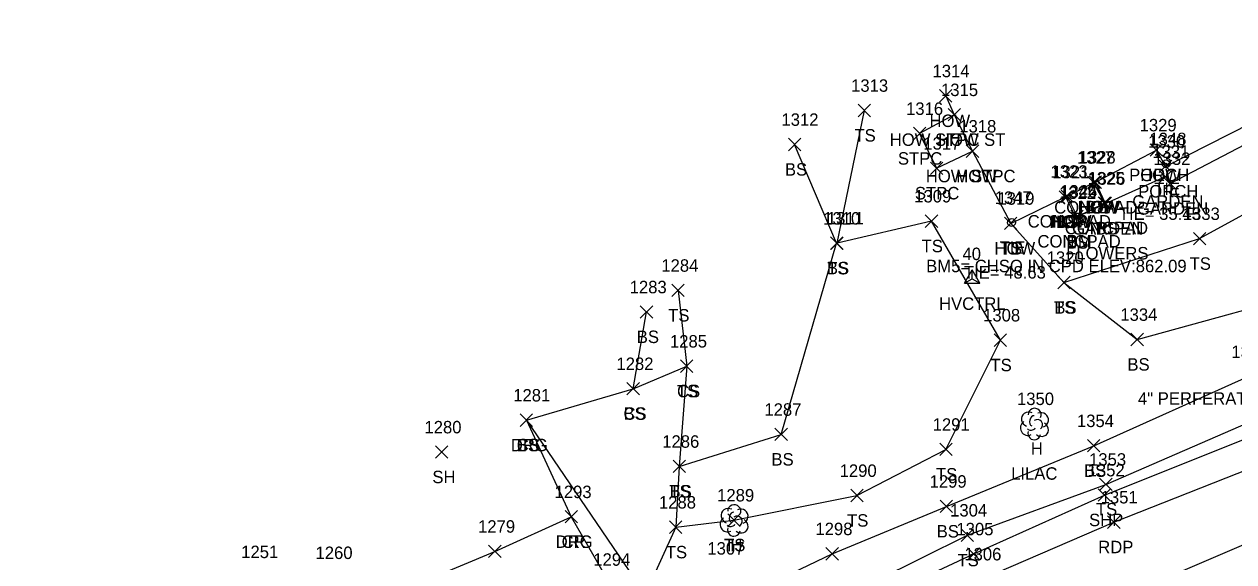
# Model space of a CAD drawing. Extents: x 1606530 to 1613020, y 784959 to 789666.
# Drawn here: x 1608865.5 to 1609059.8, y 788399 to 788485.4 of the extents above; entities that cross this region are included whole.
import ezdxf

# ---------------------------------------------------------------- set-up
doc = ezdxf.new("R2010")
doc.units = 0
for name, color, linetype in [('C_A', 7, 'Continuous'), ('C_C', 7, 'Continuous'), ('C_I', 7, 'Continuous'), ('CBP', 7, 'Continuous'), ('CPBM', 7, 'Continuous'), ('CPSM', 7, 'Continuous'), ('L_A', 7, 'Continuous'), ('L_C', 7, 'Continuous'), ('L_I', 7, 'Continuous'), ('L_TIC', 7, 'Continuous'), ('LAPB', 7, 'Continuous'), ('LBC', 7, 'Continuous'), ('LBF', 7, 'Continuous'), ('LELB', 7, 'Continuous'), ('LS', 7, 'Continuous'), ('LTD', 7, 'Continuous'), ('M_I', 7, 'Continuous'), ('P_A', 7, 'Continuous'), ('P_I', 7, 'Continuous'), ('P_TIC', 7, 'Continuous'), ('PET', 7, 'Continuous'), ('PRC', 7, 'Continuous'), ('PSP', 7, 'Continuous'), ('R_A', 7, 'Continuous'), ('R_I', 7, 'Continuous'), ('R_TIC', 7, 'Continuous'), ('RDG', 7, 'Continuous')]:
    doc.layers.add(name, color=color, linetype=linetype)

msp = doc.modelspace()

# ---------------------------------------------------------------- linework, layer by layer
at = {"layer": 'CBP'}
for centre, radius in [((1609048.95, 788462.92), 0.625), ((1609048.95, 788462.92), 0.0833), ((1609024.11, 788453.49), 0.625), ((1609024.11, 788453.49), 0.0833)]:
    msp.add_circle(centre, radius, dxfattribs=at)
at = {"layer": 'CPBM'}
for p, q in [((1609034.16, 788454.01), (1609034.16, 788455.01)), ((1609034.16, 788455.01), (1609035.16, 788455.01)), ((1609035.16, 788454.01), (1609034.16, 788454.01)), ((1609034.66, 788454.51), (1609034.66, 788454.51)), ((1609034.66, 788454.51), (1609034.66, 788454.51)), ((1609035.16, 788455.01), (1609035.16, 788454.01))]:
    msp.add_line(p, q, dxfattribs=at)
at = {"layer": 'CPSM'}
for p, q in [((1609016.53, 788443.74), (1609017.78, 788445.91)), ((1609016.53, 788443.74), (1609017.78, 788444.46)), ((1609019.03, 788443.74), (1609017.78, 788445.91)), ((1609017.78, 788444.46), (1609017.78, 788445.91)), ((1609017.78, 788444.46), (1609017.78, 788444.46)), ((1609017.78, 788444.46), (1609019.03, 788443.74)), ((1609016.53, 788443.74), (1609019.03, 788443.74))]:
    msp.add_line(p, q, dxfattribs=at)
at = {"layer": 'L_TIC'}
for points in [[(1609012.54, 788472.84), (1609014.54, 788474.84)], [(1609014.54, 788472.84), (1609012.54, 788474.84)], [(1608999.47, 788470.5), (1609001.47, 788472.5)], [(1609001.47, 788470.5), (1608999.47, 788472.5)], [(1609013.92, 788469.81), (1609015.92, 788471.81)], [(1609015.92, 788469.81), (1609013.92, 788471.81)], [(1609013.92, 788469.81), (1609015.92, 788471.81)], [(1609015.92, 788469.81), (1609013.92, 788471.81)], [(1609008.35, 788466.79), (1609010.35, 788468.79)], [(1609010.35, 788466.79), (1609008.35, 788468.79)], [(1608988.27, 788465.03), (1608990.27, 788467.03)], [(1608990.27, 788465.03), (1608988.27, 788467.03)], [(1609016.85, 788463.96), (1609018.85, 788465.96)], [(1609018.85, 788463.96), (1609016.85, 788465.96)], [(1609016.85, 788463.96), (1609018.85, 788465.96)], [(1609018.85, 788463.96), (1609016.85, 788465.96)], [(1609046.39, 788464.14), (1609048.39, 788466.14)], [(1609048.39, 788464.14), (1609046.39, 788466.14)], [(1609046.39, 788464.14), (1609048.39, 788466.14)], [(1609048.39, 788464.14), (1609046.39, 788466.14)], [(1609011.08, 788461.21), (1609013.08, 788463.21)], [(1609013.08, 788461.21), (1609011.08, 788463.21)], [(1609047.84, 788461.52), (1609049.84, 788463.52)], [(1609049.84, 788461.52), (1609047.84, 788463.52)], [(1609047.84, 788459.87), (1609049.84, 788461.87)], [(1609049.84, 788459.87), (1609047.84, 788461.87)], [(1609036.33, 788458.94), (1609038.33, 788460.94)], [(1609038.33, 788458.94), (1609036.33, 788460.94)], [(1609036.33, 788458.94), (1609038.33, 788460.94)], [(1609038.33, 788458.94), (1609036.33, 788460.94)], [(1609036.58, 788458.98), (1609038.58, 788460.98)], [(1609038.58, 788458.98), (1609036.58, 788460.98)], [(1609036.58, 788458.98), (1609038.58, 788460.98)], [(1609038.58, 788458.98), (1609036.58, 788460.98)], [(1609048.6, 788458.75), (1609050.6, 788460.75)], [(1609050.6, 788458.75), (1609048.6, 788460.75)], [(1609031.79, 788456.6), (1609033.79, 788458.6)], [(1609033.79, 788456.6), (1609031.79, 788458.6)], [(1609031.79, 788456.6), (1609033.79, 788458.6)], [(1609033.79, 788456.6), (1609031.79, 788458.6)], [(1609032.07, 788456.69), (1609034.07, 788458.69)], [(1609034.07, 788456.69), (1609032.07, 788458.69)], [(1609032.07, 788456.69), (1609034.07, 788458.69)], [(1609034.07, 788456.69), (1609032.07, 788458.69)], [(1609038.03, 788455.61), (1609040.03, 788457.61)], [(1609040.03, 788455.61), (1609038.03, 788457.61)], [(1609038.19, 788455.56), (1609040.19, 788457.56)], [(1609040.19, 788455.56), (1609038.19, 788457.56)], [(1609038.19, 788455.56), (1609040.19, 788457.56)], [(1609040.19, 788455.56), (1609038.19, 788457.56)], [(1609010.26, 788452.72), (1609012.26, 788454.72)], [(1609012.26, 788452.72), (1609010.26, 788454.72)], [(1609022.98, 788452.35), (1609024.98, 788454.35)], [(1609024.98, 788452.35), (1609022.98, 788454.35)], [(1609022.98, 788452.35), (1609024.98, 788454.35)], [(1609024.98, 788452.35), (1609022.98, 788454.35)], [(1609033.45, 788453.29), (1609035.45, 788455.29)], [(1609035.45, 788453.29), (1609033.45, 788455.29)], [(1609033.63, 788453.48), (1609035.63, 788455.48)], [(1609035.63, 788453.48), (1609033.63, 788455.48)], [(1608995.01, 788449.18), (1608997.01, 788451.18)], [(1608997.01, 788449.18), (1608995.01, 788451.18)], [(1608995.08, 788449.16), (1608997.08, 788451.16)], [(1608997.08, 788449.16), (1608995.08, 788451.16)], [(1609053.32, 788449.9), (1609055.32, 788451.9)], [(1609055.32, 788449.9), (1609053.32, 788451.9)], [(1609031.54, 788442.85), (1609033.54, 788444.85)], [(1609033.54, 788442.85), (1609031.54, 788444.85)], [(1609031.54, 788442.85), (1609033.54, 788444.85)], [(1609033.54, 788442.85), (1609031.54, 788444.85)], [(1608969.54, 788441.59), (1608971.54, 788443.59)], [(1608971.54, 788441.59), (1608969.54, 788443.59)], [(1608964.47, 788438.13), (1608966.47, 788440.13)], [(1608966.47, 788438.13), (1608964.47, 788440.13)], [(1609021.32, 788433.6), (1609023.32, 788435.6)], [(1609023.32, 788433.6), (1609021.32, 788435.6)], [(1609043.29, 788433.7), (1609045.29, 788435.7)], [(1609045.29, 788433.7), (1609043.29, 788435.7)], [(1608970.93, 788429.41), (1608972.93, 788431.41)], [(1608972.93, 788429.41), (1608970.93, 788431.41)], [(1608970.93, 788429.41), (1608972.93, 788431.41)], [(1608972.93, 788429.41), (1608970.93, 788431.41)], [(1608962.33, 788425.8), (1608964.33, 788427.8)], [(1608964.33, 788425.8), (1608962.33, 788427.8)], [(1608962.33, 788425.8), (1608964.33, 788427.8)], [(1608964.33, 788425.8), (1608962.33, 788427.8)], [(1608945.18, 788420.74), (1608947.18, 788422.74)], [(1608947.18, 788420.74), (1608945.18, 788422.74)], [(1608945.18, 788420.74), (1608947.18, 788422.74)], [(1608947.18, 788420.74), (1608945.18, 788422.74)], [(1608986.1, 788418.45), (1608988.1, 788420.45)], [(1608988.1, 788418.45), (1608986.1, 788420.45)], [(1608931.58, 788415.62), (1608933.58, 788417.62)], [(1608933.58, 788415.62), (1608931.58, 788417.62)], [(1609012.57, 788416.04), (1609014.57, 788418.04)], [(1609014.57, 788416.04), (1609012.57, 788418.04)], [(1609036.32, 788416.63), (1609038.32, 788418.63)], [(1609038.32, 788416.63), (1609036.32, 788418.63)], [(1608969.74, 788413.31), (1608971.74, 788415.31)], [(1608971.74, 788413.31), (1608969.74, 788415.31)], [(1608969.74, 788413.31), (1608971.74, 788415.31)], [(1608971.74, 788413.31), (1608969.74, 788415.31)], [(1609038.26, 788410.43), (1609040.26, 788412.43)], [(1609040.26, 788410.43), (1609038.26, 788412.43)], [(1608998.28, 788408.63), (1609000.28, 788410.63)], [(1609000.28, 788408.63), (1608998.28, 788410.63)], [(1609012.65, 788406.89), (1609014.65, 788408.89)], [(1609014.65, 788406.89), (1609012.65, 788408.89)], [(1608969.16, 788403.54), (1608971.16, 788405.54)], [(1608971.16, 788403.54), (1608969.16, 788405.54)], [(1608969.16, 788403.54), (1608971.16, 788405.54)], [(1608971.16, 788403.54), (1608969.16, 788405.54)], [(1608978.52, 788404.68), (1608980.52, 788406.68)], [(1608980.52, 788404.68), (1608978.52, 788406.68)], [(1609016.02, 788402.26), (1609018.02, 788404.26)], [(1609018.02, 788402.26), (1609016.02, 788404.26)], [(1608994.3, 788399.27), (1608996.3, 788401.27)], [(1608996.3, 788399.27), (1608994.3, 788401.27)]]:
    msp.add_lwpolyline(points, dxfattribs=at)
at = {"layer": 'LAPB'}
msp.add_lwpolyline([(1609039.19, 788456.56), (1609048.84, 788460.87), (1609049.6, 788459.75), (1609077.28, 788474.24), (1609077.03, 788475.3)], dxfattribs=at)
at = {"layer": 'LBC'}
msp.add_lwpolyline([(1609013.54, 788473.84), (1609014.92, 788470.81), (1609017.85, 788464.96), (1609023.98, 788453.35), (1609032.79, 788457.6), (1609033.07, 788457.69), (1609037.33, 788459.94), (1609037.58, 788459.98), (1609047.39, 788465.14)], dxfattribs=at)
at = {"layer": 'LBF'}
for points in [[(1609047.39, 788465.14), (1609048.84, 788462.52), (1609076.48, 788476.53), (1609071.88, 788485.36)], [(1609014.92, 788470.81), (1609009.35, 788467.79), (1609012.08, 788462.21), (1609017.85, 788464.96)]]:
    msp.add_lwpolyline(points, dxfattribs=at)
at = {"layer": 'LELB'}
for points in [[(1609023.98, 788453.35), (1609032.54, 788443.85), (1609054.32, 788450.9), (1609067.62, 788458.19), (1609077.28, 788474.24)], [(1608970.16, 788404.54), (1608979.52, 788405.68), (1608999.28, 788409.63), (1609013.57, 788417.04), (1609022.32, 788434.6), (1609011.26, 788453.72), (1608996.08, 788450.16), (1609000.47, 788471.5)], [(1608970.74, 788414.31), (1608987.1, 788419.45), (1608996.01, 788450.18), (1608989.27, 788466.03)], [(1609032.54, 788443.85), (1609044.29, 788434.7), (1609075.85, 788443.37), (1609086.62, 788465.87)], [(1609032.79, 788457.6), (1609034.45, 788454.29), (1609039.19, 788456.56), (1609037.58, 788459.98)], [(1608946.18, 788421.74), (1608965.26, 788393.75), (1608969.9, 788390.67), (1608981.43, 788393.6), (1608995.3, 788400.27), (1609013.65, 788407.89), (1609037.32, 788417.63), (1609062.12, 788428.73), (1609080.77, 788438.94), (1609090.79, 788449.89)], [(1608970.54, 788442.59), (1608971.93, 788430.41), (1608970.74, 788414.31), (1608970.16, 788404.54), (1608965.26, 788393.75)], [(1608977.62, 788385.06), (1608987.68, 788388.71), (1609017.02, 788403.26), (1609039.26, 788411.43), (1609064.66, 788422.41), (1609086.61, 788432.67), (1609091.73, 788441.2)], [(1608963.33, 788426.8), (1608965.47, 788439.13)], [(1608946.18, 788421.74), (1608963.33, 788426.8), (1608971.93, 788430.41)]]:
    msp.add_lwpolyline(points, dxfattribs=at)
at = {"layer": 'LS'}
msp.add_lwpolyline([(1609033.07, 788457.69), (1609034.63, 788454.48), (1609039.03, 788456.61), (1609037.33, 788459.94)], dxfattribs=at)
at = {"layer": 'LTD'}
for p, q in [((1609027.77, 788421.17), (1609027.77, 788421.17)), ((1609027.77, 788421.17), (1609027.77, 788421.17)), ((1608979.52, 788405.68), (1608979.52, 788405.68)), ((1608979.52, 788405.68), (1608979.52, 788405.68))]:
    msp.add_line(p, q, dxfattribs=at)
for centre in [(1609027.82, 788422.61), (1608979.57, 788407.11)]:
    msp.add_arc(centre, 1.05, 335.5272, 180.9563, dxfattribs=at)
for centre, major_axis, ratio, start_param, end_param in [((1609026.98, 788421.84), (1.21, -0.51), 0.895232, 1.570796, 4.712389), ((1609028.81, 788421.76), (-1.14, -0.48), 0.949671, 1.570796, 4.712389), ((1609026.69, 788420.46), (0.58, -1.04), 0.959034, 3.141593, 6.283185), ((1609027.56, 788421.63), (-0.208, -0.792), 0.645439, 3.141593, 6.283185), ((1609028.27, 788421.01), (-0.5, 0.667), 0.989748, 3.141593, 6.283185), ((1609028.77, 788420.34), (-1.09, 0.79), 0.841452, 1.570796, 4.712389), ((1609027.77, 788419.67), (0.26, 1.06), 0.942809, 1.570796, 4.712389), ((1609027.31, 788420.42), (-0.625, -0.083), 0.423636, 0, 3.141593), ((1608978.73, 788406.34), (1.21, -0.51), 0.895232, 1.570796, 4.712389), ((1608980.56, 788406.26), (-1.14, -0.48), 0.949671, 1.570796, 4.712389), ((1608978.44, 788404.97), (0.58, -1.04), 0.959034, 3.141593, 6.283185), ((1608979.31, 788406.14), (-0.208, -0.792), 0.645439, 3.141593, 6.283185), ((1608980.02, 788405.51), (-0.5, 0.667), 0.989748, 3.141593, 6.283185), ((1608980.52, 788404.84), (-1.09, 0.79), 0.841452, 1.570796, 4.712389), ((1608979.52, 788404.18), (0.26, 1.06), 0.942809, 1.570796, 4.712389), ((1608979.06, 788404.93), (-0.625, -0.083), 0.423636, 0, 3.141593)]:
    msp.add_ellipse(centre, major_axis=major_axis, ratio=ratio, start_param=start_param, end_param=end_param, dxfattribs=at)
at = {"layer": 'P_TIC'}
for points in [[(1609038.03, 788408.71), (1609040.03, 788410.71)], [(1609040.03, 788408.71), (1609038.03, 788410.71)], [(1608952.39, 788405.22), (1608954.39, 788407.22)], [(1608954.39, 788405.22), (1608952.39, 788407.22)], [(1609039.55, 788404.36), (1609041.55, 788406.36)], [(1609041.55, 788404.36), (1609039.55, 788406.36)], [(1608940.11, 788399.66), (1608942.11, 788401.66)], [(1608942.11, 788399.66), (1608940.11, 788401.66)], [(1609017.03, 788399.24), (1609019.03, 788401.24)], [(1609019.03, 788399.24), (1609017.03, 788401.24)]]:
    msp.add_lwpolyline(points, dxfattribs=at)
at = {"layer": 'PET'}
msp.add_lwpolyline([(1608858.1, 788310.73), (1608896.56, 788332.46), (1608932.58, 788352.68), (1608960.4, 788367.21), (1608987.92, 788381.26), (1609019.36, 788396.21), (1609040.55, 788405.36), (1609066.48, 788415.58), (1609102.05, 788427.76), (1609127.71, 788434.8)], dxfattribs=at)
at = {"layer": 'PRC'}
for points in [[(1608863.25, 788300.9), (1608901.81, 788322.6), (1608937.61, 788342.72), (1608976.12, 788362.76), (1609017.58, 788382.95), (1609062.58, 788402.24), (1609089.79, 788412.89), (1609118.81, 788421.44), (1609162.84, 788431.75), (1609194.15, 788437.36), (1609237.64, 788442.85), (1609286.9, 788446.16), (1609332.71, 788446.44), (1609379.39, 788445.34), (1609425.62, 788443.43), (1609445.83, 788442.47), (1609477.78, 788440.95), (1609519.76, 788438.85), (1609569.72, 788435.9), (1609601.73, 788434.31), (1609642.39, 788431.82), (1609682.03, 788429.15), (1609726.55, 788426.79)], [(1608923.92, 788393.47), (1608941.11, 788400.66), (1608953.39, 788406.22)]]:
    msp.add_lwpolyline(points, dxfattribs=at)
at = {"layer": 'PSP'}
msp.add_lwpolyline([(1608855.39, 788314.11), (1608894.81, 788336.59), (1608931.25, 788356.38), (1608958.6, 788370.93), (1608985.98, 788385.27), (1609018.03, 788400.24), (1609039.03, 788409.71), (1609065.41, 788420.26), (1609085.95, 788428.61), (1609114.12, 788436.45)], dxfattribs=at)
at = {"layer": 'R_TIC'}
for points in [[(1608945.18, 788420.74), (1608947.18, 788422.74)], [(1608947.18, 788420.74), (1608945.18, 788422.74)], [(1608952.39, 788405.22), (1608954.39, 788407.22)], [(1608954.39, 788405.22), (1608952.39, 788407.22)]]:
    msp.add_lwpolyline(points, dxfattribs=at)
at = {"layer": 'RDG'}
msp.add_lwpolyline([(1608946.18, 788421.74), (1608953.39, 788406.22), (1608959.62, 788395.35), (1608968.35, 788387.21), (1608977.62, 788385.06)], dxfattribs=at)

# ---------------------------------------------------------------- texts
at = {"layer": 'C_A'}
for s, p in [('TIE', (1609047.03, 788457.92)), ('TIE', (1609022.19, 788448.49)), ('BM', (1609032.98, 788449.51)), ('HVCTRL', (1609012.47, 788439.46))]:
    msp.add_text(s, height=2, dxfattribs=at).set_placement(p)
at = {"layer": 'C_C'}
for s, p in [('TIE= 35.45', (1609041.36, 788453.92)), ('BM5= CHSQ IN CPD ELEV:862.09', (1609010.4, 788445.51)), ('TIE= 48.63', (1609016.47, 788444.49)), ('4" PERFERATED ASPHALT PIPE (', (1609044.42, 788424.22))]:
    msp.add_text(s, height=2, dxfattribs=at).set_placement(p)
at = {"layer": 'C_I'}
for s, p in [('1348', (1609046.26, 788465.92)), ('1347', (1609021.41, 788456.49)), ('1346', (1609031.91, 788457.51)), ('40', (1609016.23, 788447.46))]:
    msp.add_text(s, height=2, dxfattribs=at).set_placement(p)
at = {"layer": 'L_A'}
for s, p in [('HOW', (1609010.93, 788468.84)), ('TS', (1608998.88, 788466.5)), ('HOW STPC ST', (1609004.55, 788465.81)), ('HOW', (1609012.3, 788465.81)), ('STPC', (1609005.86, 788462.79)), ('BS', (1608987.71, 788461.03)), ('HOW STPC', (1609010.34, 788459.96)), ('HOW', (1609015.23, 788459.96)), ('PORCH', (1609043.01, 788460.14)), ('HOW', (1609044.78, 788460.14)), ('STPC', (1609008.59, 788457.21)), ('GARDEN', (1609043.51, 788455.87)), ('PORCH', (1609044.46, 788457.52)), ('CONCPAD', (1609030.97, 788454.94)), ('HOW', (1609034.71, 788454.94)), ('HOW', (1609034.97, 788454.98)), ('BS', (1609036.02, 788454.98)), ('GARDEN', (1609044.27, 788454.75)), ('CONCPAD', (1609026.71, 788452.69)), ('HOW', (1609030.18, 788452.6)), ('HOW', (1609030.45, 788452.69)), ('BS', (1609031.23, 788452.6)), ('CONCPAD', (1609032.67, 788451.61)), ('GARDEN', (1609033.85, 788451.56)), ('BS', (1609037.63, 788451.56)), ('TS', (1609009.67, 788448.72)), ('HOW', (1609021.37, 788448.35)), ('TS', (1609022.39, 788448.35)), ('CONCPAD', (1609028.28, 788449.48)), ('BS', (1609032.89, 788449.29)), ('TS', (1608994.49, 788445.16)), ('BS', (1608994.45, 788445.18)), ('TS', (1609052.73, 788445.9)), ('TS', (1609030.95, 788438.85)), ('BS', (1609030.99, 788438.85)), ('TS', (1608968.95, 788437.59)), ('BS', (1608963.91, 788434.13)), ('TS', (1609020.73, 788429.6)), ('BS', (1609042.73, 788429.7)), ('TS', (1608970.34, 788425.41)), ('CS', (1608970.37, 788425.41)), ('CS', (1608961.77, 788421.8)), ('BS', (1608961.77, 788421.8)), ('CS', (1608944.62, 788416.74)), ('BS', (1608944.62, 788416.74)), ('H', (1609027.21, 788416.17)), ('BS', (1608985.54, 788414.45)), ('SH', (1608931.07, 788411.62)), ('TS', (1609011.98, 788412.04)), ('BS', (1609035.76, 788412.63)), ('TS', (1608969.15, 788409.31)), ('BS', (1608969.18, 788409.31)), ('TS', (1609037.67, 788406.43)), ('TS', (1608997.69, 788404.63)), ('BS', (1609012.09, 788402.89)), ('TS', (1608968.57, 788399.54)), ('TS', (1608968.57, 788399.54)), ('TS', (1608977.93, 788400.68)), ('H', (1608978.95, 788400.68)), ('TS', (1609015.43, 788398.26))]:
    msp.add_text(s, height=2, dxfattribs=at).set_placement(p)
at = {"layer": 'L_C'}
for s, p in [('FLOWERS', (1609032.89, 788447.56)), ('LILAC', (1609024.05, 788412.17))]:
    msp.add_text(s, height=2, dxfattribs=at).set_placement(p)
at = {"layer": 'L_I'}
for s, p in [('1314', (1609011.42, 788476.84)), ('1313', (1608998.34, 788474.5)), ('1315', (1609012.79, 788473.81)), ('1315', (1609012.79, 788473.81)), ('1316', (1609007.17, 788470.79)), ('1312', (1608987.15, 788469.03)), ('1318', (1609015.72, 788467.96)), ('1318', (1609015.72, 788467.96)), ('1329', (1609044.69, 788468.14)), ('1329', (1609044.69, 788468.14)), ('1330', (1609046.06, 788465.52)), ('1317', (1609009.95, 788465.21)), ('1331', (1609046.72, 788463.87)), ('1327', (1609034.64, 788462.94)), ('1327', (1609034.64, 788462.94)), ('1328', (1609034.89, 788462.98)), ('1328', (1609034.89, 788462.98)), ('1332', (1609046.9, 788462.75)), ('1323', (1609030.38, 788460.69)), ('1323', (1609030.38, 788460.69)), ('1321', (1609030.66, 788460.6)), ('1321', (1609030.66, 788460.6)), ('1325', (1609036.33, 788459.61)), ('1326', (1609036.44, 788459.56)), ('1326', (1609036.44, 788459.56)), ('1309', (1609008.48, 788456.72)), ('1319', (1609021.85, 788456.35)), ('1319', (1609021.85, 788456.35)), ('1322', (1609031.75, 788457.29)), ('1324', (1609031.94, 788457.48)), ('1333', (1609051.63, 788453.9)), ('1310', (1608993.86, 788453.16)), ('1311', (1608994.45, 788453.18)), ('1320', (1609029.76, 788446.85)), ('1320', (1609029.76, 788446.85)), ('1284', (1608967.85, 788445.59)), ('1283', (1608962.77, 788442.13)), ('1308', (1609019.55, 788437.6)), ('1334', (1609041.59, 788437.7)), ('1285', (1608969.24, 788433.41)), ('1285', (1608969.24, 788433.41)), ('1355', (1609059.43, 788431.73)), ('1282', (1608960.64, 788429.8)), ('1282', (1608960.64, 788429.8)), ('1281', (1608944.06, 788424.74)), ('1281', (1608944.06, 788424.74)), ('1350', (1609024.99, 788424.17)), ('1287', (1608984.41, 788422.45)), ('1280', (1608929.8, 788419.62)), ('1291', (1609011.44, 788420.04)), ('1354', (1609034.62, 788420.63)), ('1286', (1608968, 788417.31)), ('1286', (1608968, 788417.31)), ('1353', (1609036.57, 788414.43)), ('1290', (1608996.5, 788412.63)), ('1299', (1609010.95, 788410.89)), ('1288', (1608967.47, 788407.54)), ('1288', (1608967.47, 788407.54)), ('1289', (1608976.82, 788408.68)), ('1289', (1608976.82, 788408.68)), ('1304', (1609014.25, 788406.26)), ('1298', (1608992.61, 788403.27))]:
    msp.add_text(s, height=2, dxfattribs=at).set_placement(p)
at = {"layer": 'M_I'}
msp.add_text('1307', height=2, dxfattribs=at).set_placement((1608975.25, 788400.14))
at = {"layer": 'P_A'}
for s, p in [('SHP', (1609036.57, 788404.71)), ('CR', (1608951.83, 788401.22)), ('RDP', (1609038.04, 788400.36))]:
    msp.add_text(s, height=2, dxfattribs=at).set_placement(p)
at = {"layer": 'P_I'}
for s, p in [('1352', (1609036.34, 788412.71)), ('1293', (1608950.7, 788409.22)), ('1351', (1609038.43, 788408.36)), ('1279', (1608938.41, 788403.66)), ('1305', (1609015.26, 788403.24)), ('1294', (1608956.92, 788398.35)), ('1306', (1609016.53, 788399.21))]:
    msp.add_text(s, height=2, dxfattribs=at).set_placement(p)
at = {"layer": 'R_A'}
for p in [(1608943.67, 788416.74), (1608950.88, 788401.22)]:
    msp.add_text('DRG', height=2, dxfattribs=at).set_placement(p)
at = {"layer": 'R_I'}
for s, p in [('1281', (1608944.06, 788424.74)), ('1293', (1608950.7, 788409.22)), ('1251', (1608900.36, 788399.58)), ('1260', (1608912.3, 788399.43)), ('1294', (1608956.92, 788398.35))]:
    msp.add_text(s, height=2, dxfattribs=at).set_placement(p)

doc.saveas('drawing.dxf')
